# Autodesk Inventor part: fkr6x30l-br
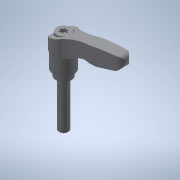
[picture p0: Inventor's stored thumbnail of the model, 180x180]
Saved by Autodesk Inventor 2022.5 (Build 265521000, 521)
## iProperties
Created: 2017-09
Part Number: fkr6x30l-br
Material: 一般
Document SubType Name: Modeling
Designer: imaocorp
Density: 1 g/cm^3
Appearance: 既定
Author: imaocorp
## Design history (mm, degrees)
node "fkr6x30l-br.x_t1"
node "fkr6x30l-br"
node "Base1"
